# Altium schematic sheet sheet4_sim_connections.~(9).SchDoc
size A3; Author: Mauri Shadi; CompanyName: BFH; DrawnBy: Mauri Shadi; SheetNumber: 2; SheetTotal: 3
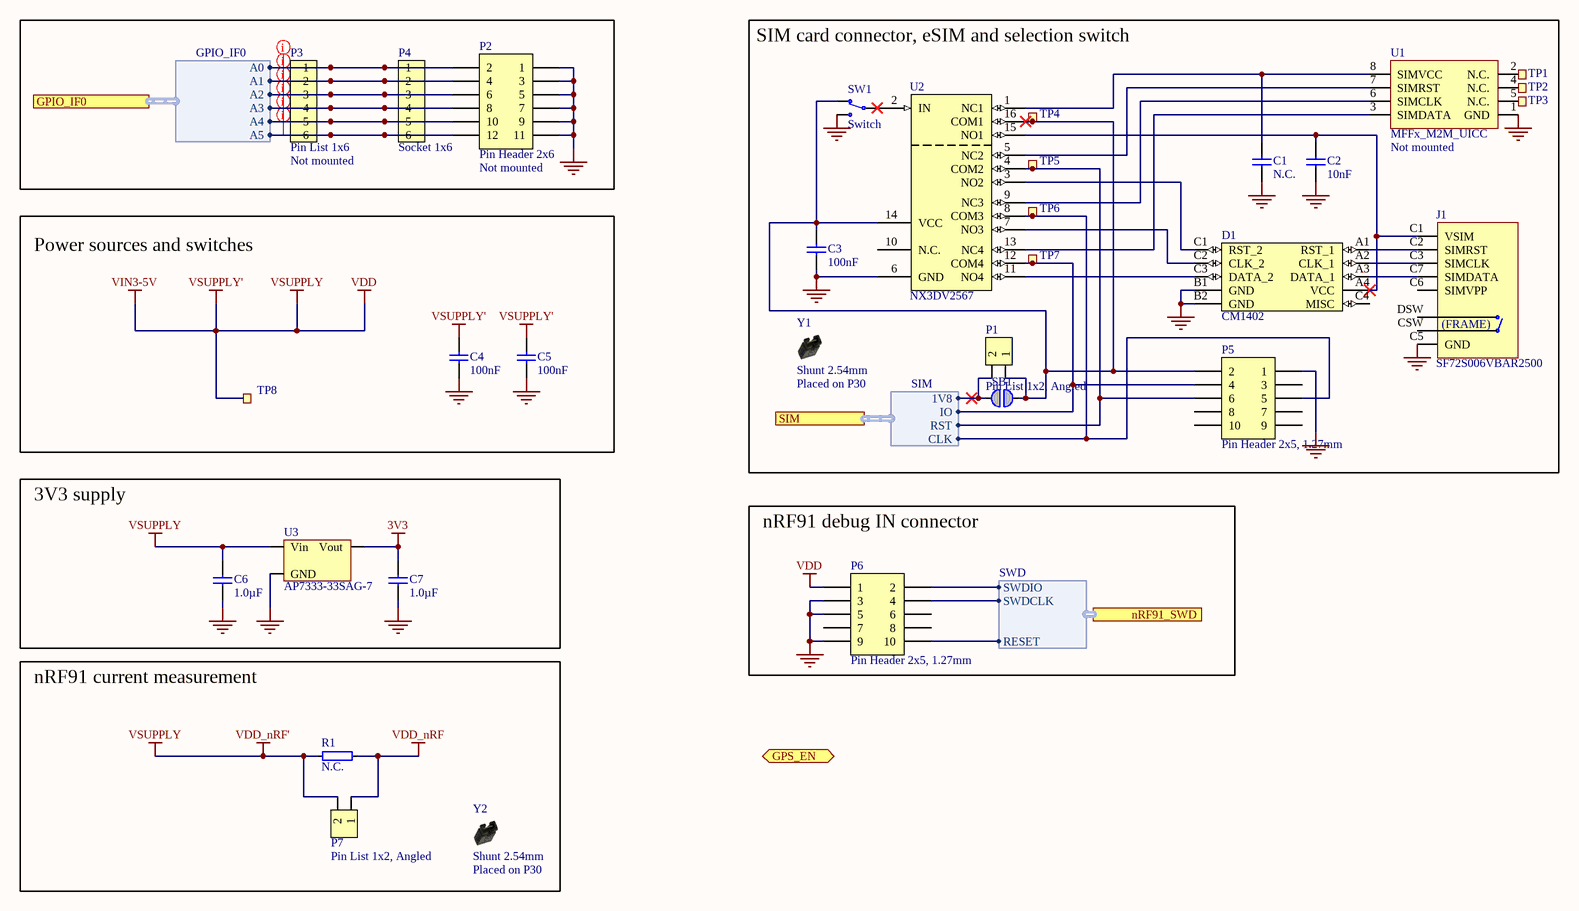
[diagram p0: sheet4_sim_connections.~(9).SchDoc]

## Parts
C1  N.C.  [CAPC0603X03L_C_NC]
C2  10nF  [CAPC0603X03L_C]
C3  100nF  [CAPC0603X03L_C]
C4  100nF  [CAPC0603X03L_C]
C5  100nF  [CAPC0603X03L_C]
C6  1.0µF  [CAPC0603X03L_C]
C7  1.0µF  [CAPC0603X03L_C]
D1  CM1402  [CM1402]
J1  SF72S006VBAR2500  [SF72S006VBAR2500]
P1  Pin List 1x2, Angled  [LIST_ANG_1x2-SMD-2.54MM]
P2  Pin Header 2x6  Assembly: Not mounted  [HDR_2x6-NC]
P3  Pin List 1x6  Assembly: Not mounted  [LIST_1x6_SMD-NC]
P4  Socket 1x6  [SOCKET_1x6_SMD]
P5  Pin Header 2x5, 1.27mm  [HDR_2x5-SMD-1.27mm]
P6  Pin Header 2x5, 1.27mm  [HDR_2x5-SMD-1.27mm-K]
P7  Pin List 1x2, Angled  [LIST_ANG_1x2-SMD-2.54MM]
R1  N.C.  [RESC1005X04L_NC]
SB1  Solderbridge  [Solderbridge]  (value not drawn)  (no BOM)
SW1  Switch  [CJS-120xA]
TP1  Ø1.0mm,SMD  [TP_SMD_D1.0mm]  (value not drawn)  (no BOM)
TP2  Ø1.0mm,SMD  [TP_SMD_D1.0mm]  (value not drawn)  (no BOM)
TP3  Ø1.0mm,SMD  [TP_SMD_D1.0mm]  (value not drawn)  (no BOM)
TP4  Ø1.5mm,SMD  [TP_SMD_D1.5mm]  (value not drawn)  (no BOM)
TP5  Ø1.5mm,SMD  [TP_SMD_D1.5mm]  (value not drawn)  (no BOM)
TP6  Ø1.5mm,SMD  [TP_SMD_D1.5mm]  (value not drawn)  (no BOM)
TP7  Ø1.5mm,SMD  [TP_SMD_D1.5mm]  (value not drawn)  (no BOM)
TP8  Ø1.5mm,SMD  [TP_SMD_D1.5mm]  (value not drawn)  (no BOM)
U1  MFFx_M2M_UICC  Assembly: Not mounted  [SON127P600X90_HS-8N]
U2  NX3DV2567  [XQFN40P180X260X50-16N]
U3  AP7333-33SAG-7  [SOT-23A]
Y1  Shunt 2.54mm  Assembly: Placed on P30  [Shunt_2.54mm_Horizontal]
Y2  Shunt 2.54mm  Assembly: Placed on P30  [Shunt_2.54mm_Horizontal]

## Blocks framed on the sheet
SIM card connector, eSIM and selection switch: C1-C3 D1 J1 P1 P5 SB1 SW1 TP1-TP7 U1 U2 Y1
Power sources and switches: C4 C5 TP8
3V3 supply: C6 C7 U3
nRF91 debug IN connector: P6
nRF91 current measurement: P7 R1 Y2

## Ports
GPIO_IF0 (harness GPIO_IF0, see sheet1_connections[4B], sheet2_nRF9160[7C]), GPS_EN (bidir, see sheet1_connections[4B], sheet2_nRF9160[7C]), nRF91_SWD (harness SWD, see sheet1_connections[4B], sheet2_nRF9160[7C]), SIM (harness SIM, see sheet1_connections[4B], sheet2_nRF9160[7D])

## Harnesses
SWD: SWDIO, SWDCLK, RESET
GPIO_IF0: A0, A1, A2, A3, A4, A5
SIM: CLK, IO, 1V8, RST

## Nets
3V3: C7.1 U3.2(Vout)
GND: C1.1 C2.2 C3.1 C4.2 C5.1 C6.2 C7.2 D1.B1(GND) D1.B2(GND) J1.0(GND) J1.C5(GND) P2.1 P2.3 P2.5 P2.7 P2.9 P2.11 P5.1 P6.3 P6.5 P6.9 SW1.3(N.O) U1.1(GND) U2.6(GND) U3.3(GND)
VDD: C4.1 C5.2 C6.1 P6.1 P7.2 R1.2 TP8.1 U3.1(Vin)  [also labelled VDD_nRF', VIN3-5V, VSUPPLY, VSUPPLY']
VDD_nRF: P7.1 R1.1
NetC1_2: C1.2 U1.8(SIMVCC) U2.1(NC1)
NetC2_1: C2.1 D1.A4(VCC) J1.C1(VSIM) U2.15(NO1)
NetC3_2: C3.2 P1.1 P5.2 SB1.2 SW1.1(N.C) TP4.1 U2.14(VCC) U2.16(COM1)
NetD1_A1: D1.A1(RST_1) J1.C2(SIMRST)
NetD1_A2: D1.A2(CLK_1) J1.C3(SIMCLK)
NetD1_A3: D1.A3(DATA_1) J1.C7(SIMDATA)
NetD1_C1: D1.C1(RST_2) U2.3(NO2)
NetD1_C2: D1.C2(CLK_2) U2.7(NO3)
NetD1_C3: D1.C3(DATA_2) U2.11(NO4)
NetP1_2: P1.2 SB1.1 ; port SIM.1V8
NetP2_2: P2.2 P3.1 P4.1 ; port GPIO_IF0.A0
NetP2_4: P2.4 P3.2 P4.2 ; port GPIO_IF0.A1
NetP2_6: P2.6 P3.3 P4.3 ; port GPIO_IF0.A2
NetP2_8: P2.8 P3.4 P4.4 ; port GPIO_IF0.A3
NetP2_10: P2.10 P3.5 P4.5 ; port GPIO_IF0.A4
NetP2_12: P2.12 P3.6 P4.6 ; port GPIO_IF0.A5
NetP5_4: P5.4 TP7.1 U2.12(COM4) ; port SIM.IO
NetP5_5: P5.5 TP6.1 U2.8(COM3) ; port SIM.CLK
NetP5_6: P5.6 TP5.1 U2.4(COM2) ; port SIM.RST
NetP6_2: P6.2 ; port nRF91_SWD.SWDIO
NetP6_4: P6.4 ; port nRF91_SWD.SWDCLK
NetP6_10: P6.10 ; port nRF91_SWD.RESET
NetSW1_2: SW1.2(COM) U2.2(IN)
NetTP1_1: TP1.1 U1.2(N.C.)
NetTP2_1: TP2.1 U1.4(N.C.)
NetTP3_1: TP3.1 U1.5(N.C.)
NetU1_3: U1.3(SIMDATA) U2.13(NC4)
NetU1_6: U1.6(SIMCLK) U2.9(NC3)
NetU1_7: U1.7(SIMRST) U2.5(NC2)

Not connected (* = marked no-connect by the designer): D1 C4(MISC); J1 C6(SIMVPP) CSW DSW; P5 3 7 8 9 10; P6 6 7 8; U2 10(N.C.)

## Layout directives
net class GPIO: NetP2_2, NetP2_4, NetP2_6, NetP2_8, NetP2_10, NetP2_12

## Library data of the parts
C1 = C0201-N.C.: Not mounted; Manufacturer: N.A.; Note: Chip Cap; Assembly: Not mounted; Pad Count: 2
C2 = C0201-10n: Capacitor, X7R, ±10%; Manufacturer: N.A.; Part number IPS: 00000003480; Note: 10V; Pad Count: 2
C3-C5 = C0201-100n: Capacitor, X5R, ±10%; Manufacturer: N.A.; Part number IPS: 00000001248, 00000002505; Note: 16V; Pad Count: 2
C6 C7 = C0201-1µ0: Capacitor, X5R, ±10%; Manufacturer: N.A.; Part number IPS: 00000001723; Note: 10V; Pad Count: 2
D1 = CM1402: EMI Network Filter Arrays SIM CARD EMI FILTER WITH ESD PROTECTION; Manufacturer: ON Semiconductor; Manufacturer Part Number: CM1402-03CP; Part number IPS: 00000009949; Note: N.A.; Pad Count: 10
J1 = SF72S006VBAR2500: n 8 (6 + 2) Position Card Connector NANO SIM Surface Mount, Right Angle Gold; Manufacturer: JAE Electronics; Part number IPS: 00000009956; Note: N.A.; Pad Count: 8
P1 P7 = Pin List Ang 1x2 SMD, 2.54mm: Pin List 1x2, 2.54mm (100mil), Right Angled, SMD; Manufacturer: W-CON; Manufacturer Part Number: 1125B-1102S0Z135R2; Part number IPS: 00000009972; Note: N.A.; Artikkelnr Noca: 55010023; Pad Count: 2
P2 = Pin Header 2x6, N.C.: Pin Header 2x6, 2.54mm (100mil); Manufacturer: N.A.; Pad Count: 12
P3 = Pin List 1x6 SMD, N.C.: Pin List 1x6, 2.54mm (100mil), SMD; Manufacturer: W-CON; Manufacturer Part Number: 1125-1106S0M116R2; Note: N.A.; Artikkelnr Noca: 55010026; Pad Count: 6
P4 = Socket 1x6 SMD: Socket 1x6, 2.54mm (100mil), SMD; Manufacturer: W-CON; Manufacturer Part Number: 2171-106MS0CUNR1; Part number IPS: 00000009964; Note: N.A.; Artikkelnr Noca: 55030001; Pad Count: 6
P5 = Pin Header 2x5 SMD, 1.27mm: Pin Header 2x5, 1.27mm (50mil), SMD; Manufacturer: W-CON; Manufacturer Part Number: 1325-1205S0M078R1; Part number IPS: 00000009970; Note: N.A.; Artikkelnr Noca: 55019196; Pad Count: 10
P6 = Pin Header 2x5 SMD, 1.27mm, KS: Pin Header 2x5, 1.27mm (50mil), SMD, Keying Shroud; Manufacturer: W-CON; Manufacturer Part Number: 3132-10MS0BK00R1; Part number IPS: 00000009968; Note: N.A.; Artikkelnr Noca: 55010009; Pad Count: 10
R1 = R0402-N.C.: Not mounted; Manufacturer: N.A.; Note: Chip Res; Assembly: Not mounted; Pad Count: 2
SB1 = Solderbridge: Manufacturer: N.A.; Pad Count: 2
SW1 = CJS-1200TA: SMD slide Switch (ON-ON); Manufacturer: Copal Electronics Inc; Part number IPS: 00000009982; Note: N.A.; Artikkelnr Noca: 50019068; Pad Count: 3
TP1-TP3 = TP_SMD_Ø1.0MM: 1.0mm circular SMD testpad; Manufacturer: Nordic Semiconductor; Manufacturer Part Number: N.A.; Pad Count: 1
TP4-TP8 = TP_SMD_Ø1.5MM: 1.5mm circular SMD testpad; Manufacturer: Nordic Semiconductor; Manufacturer Part Number: N.A.; Pad Count: 1
U1 = M2M_UICC: M2M UICC SIM Card; Manufacturer: N.A.; Pad Count: 8
U2 = NX3DV2567GU: Low-ohmic four-pole double-throw analog switch; Manufacturer: NXP Semiconductors; Part number IPS: 00000007816; Note: N.A.; Artikkelnr Noca: 15079317; Pad Count: 16
U3 = AP7333-33SAG-7: 300mA, Low Quiescent Current, Fast Transient Low Dropout Linear Regulator; Manufacturer: Diodes Incorporated; Part number IPS: 00000001673; Note: N.A.; Artikkelnr Noca: 17039216; Pad Count: 3
Y1 = SHUNT JUMPER 2.54mm BLACK GOLD Horizontal (obsolete): Shunt Jumper 2.54mm Black; Manufacturer: N.A.; Part number IPS: 00000001916; Note: SHUNT JUMPER .1" BLACK GOLD, h=6.00mm, w=5.00mm; Artikkelnr Noca: 56099001; Pad Count: 2
Y2 = SHUNT JUMPER 2.54mm BLACK GOLD Horizontal (Obsolete): Shunt Jumper 2.54mm Black; Manufacturer: N.A.; Part number IPS: 00000001916; Note: SHUNT JUMPER .1" BLACK GOLD, h=6.00mm, w=5.00mm; Artikkelnr Noca: 56099001; Pad Count: 2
